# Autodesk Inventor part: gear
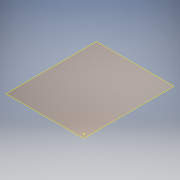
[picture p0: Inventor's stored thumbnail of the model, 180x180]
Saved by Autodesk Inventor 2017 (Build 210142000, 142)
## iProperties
Created: 2017-05
Part Number: gear
Material: Generic
Document SubType Name: Modeling
Designer: 1717440
Density: 1 g/cm^3
Appearance: Default
Author: 1717440
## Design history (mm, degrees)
workplane "Work Plane1"
sketch "Sketch1"
  geometry: 1 further point
  constraints: 1 other
